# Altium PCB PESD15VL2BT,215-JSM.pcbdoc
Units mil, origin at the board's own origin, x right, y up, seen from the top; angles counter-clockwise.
Board outline 623.63 x 620 mil, 2 copper layers (Top Layer, Bottom Layer), stack 0 mil thick; 1 components, 0 nets, 3 pads, 0 vias.
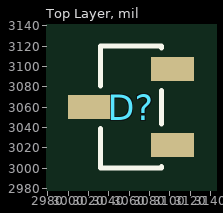
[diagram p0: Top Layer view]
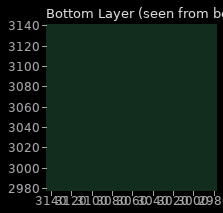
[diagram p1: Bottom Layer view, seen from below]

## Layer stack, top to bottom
Top Layer: signal copper (thickness not stored)
Bottom Layer: signal copper (thickness not stored)

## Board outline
3373.63,2750 2750,2750 2750,3370 3373.63,3370

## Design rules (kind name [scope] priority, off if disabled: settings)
PasteMaskExpansion "Paste Mask Expansion" [All] p1: expansion=0
SolderMaskExpansion "Solder Mask Expansion" [IsVia] p1: expansion=-1000 istentingtop=TRUE
SolderMaskExpansion "Solder Mask Expansion" [All] p2: expansion=2 istentingtop=FALSE

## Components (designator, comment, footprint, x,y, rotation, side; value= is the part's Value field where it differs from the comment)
D? "PESD15VL2BT,215-JSM" SOT-23-3_L2.9-W1.4-P1.90-LS2.5-BR 3061.81,3060 r0 top

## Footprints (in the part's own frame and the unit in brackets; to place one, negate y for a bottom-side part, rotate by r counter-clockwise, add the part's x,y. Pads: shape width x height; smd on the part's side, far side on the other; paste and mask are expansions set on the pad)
SOT-23-3_L2.9-W1.4-P1.90-LS2.5-BR [mm]
  rect 1.07x0.6 smd: 1(1.035,-0.95) 2(1.035,0.95) 3(-1.035,0)
  silkscreen extent -0.76,-1.52 0.76,1.52

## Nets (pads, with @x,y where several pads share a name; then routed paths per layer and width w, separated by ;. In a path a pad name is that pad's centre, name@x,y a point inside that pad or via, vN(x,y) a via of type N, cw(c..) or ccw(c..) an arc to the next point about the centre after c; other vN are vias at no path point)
pads on no net: D?.1 D?.2 D?.3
